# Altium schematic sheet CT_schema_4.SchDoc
size 461 x 327 mm
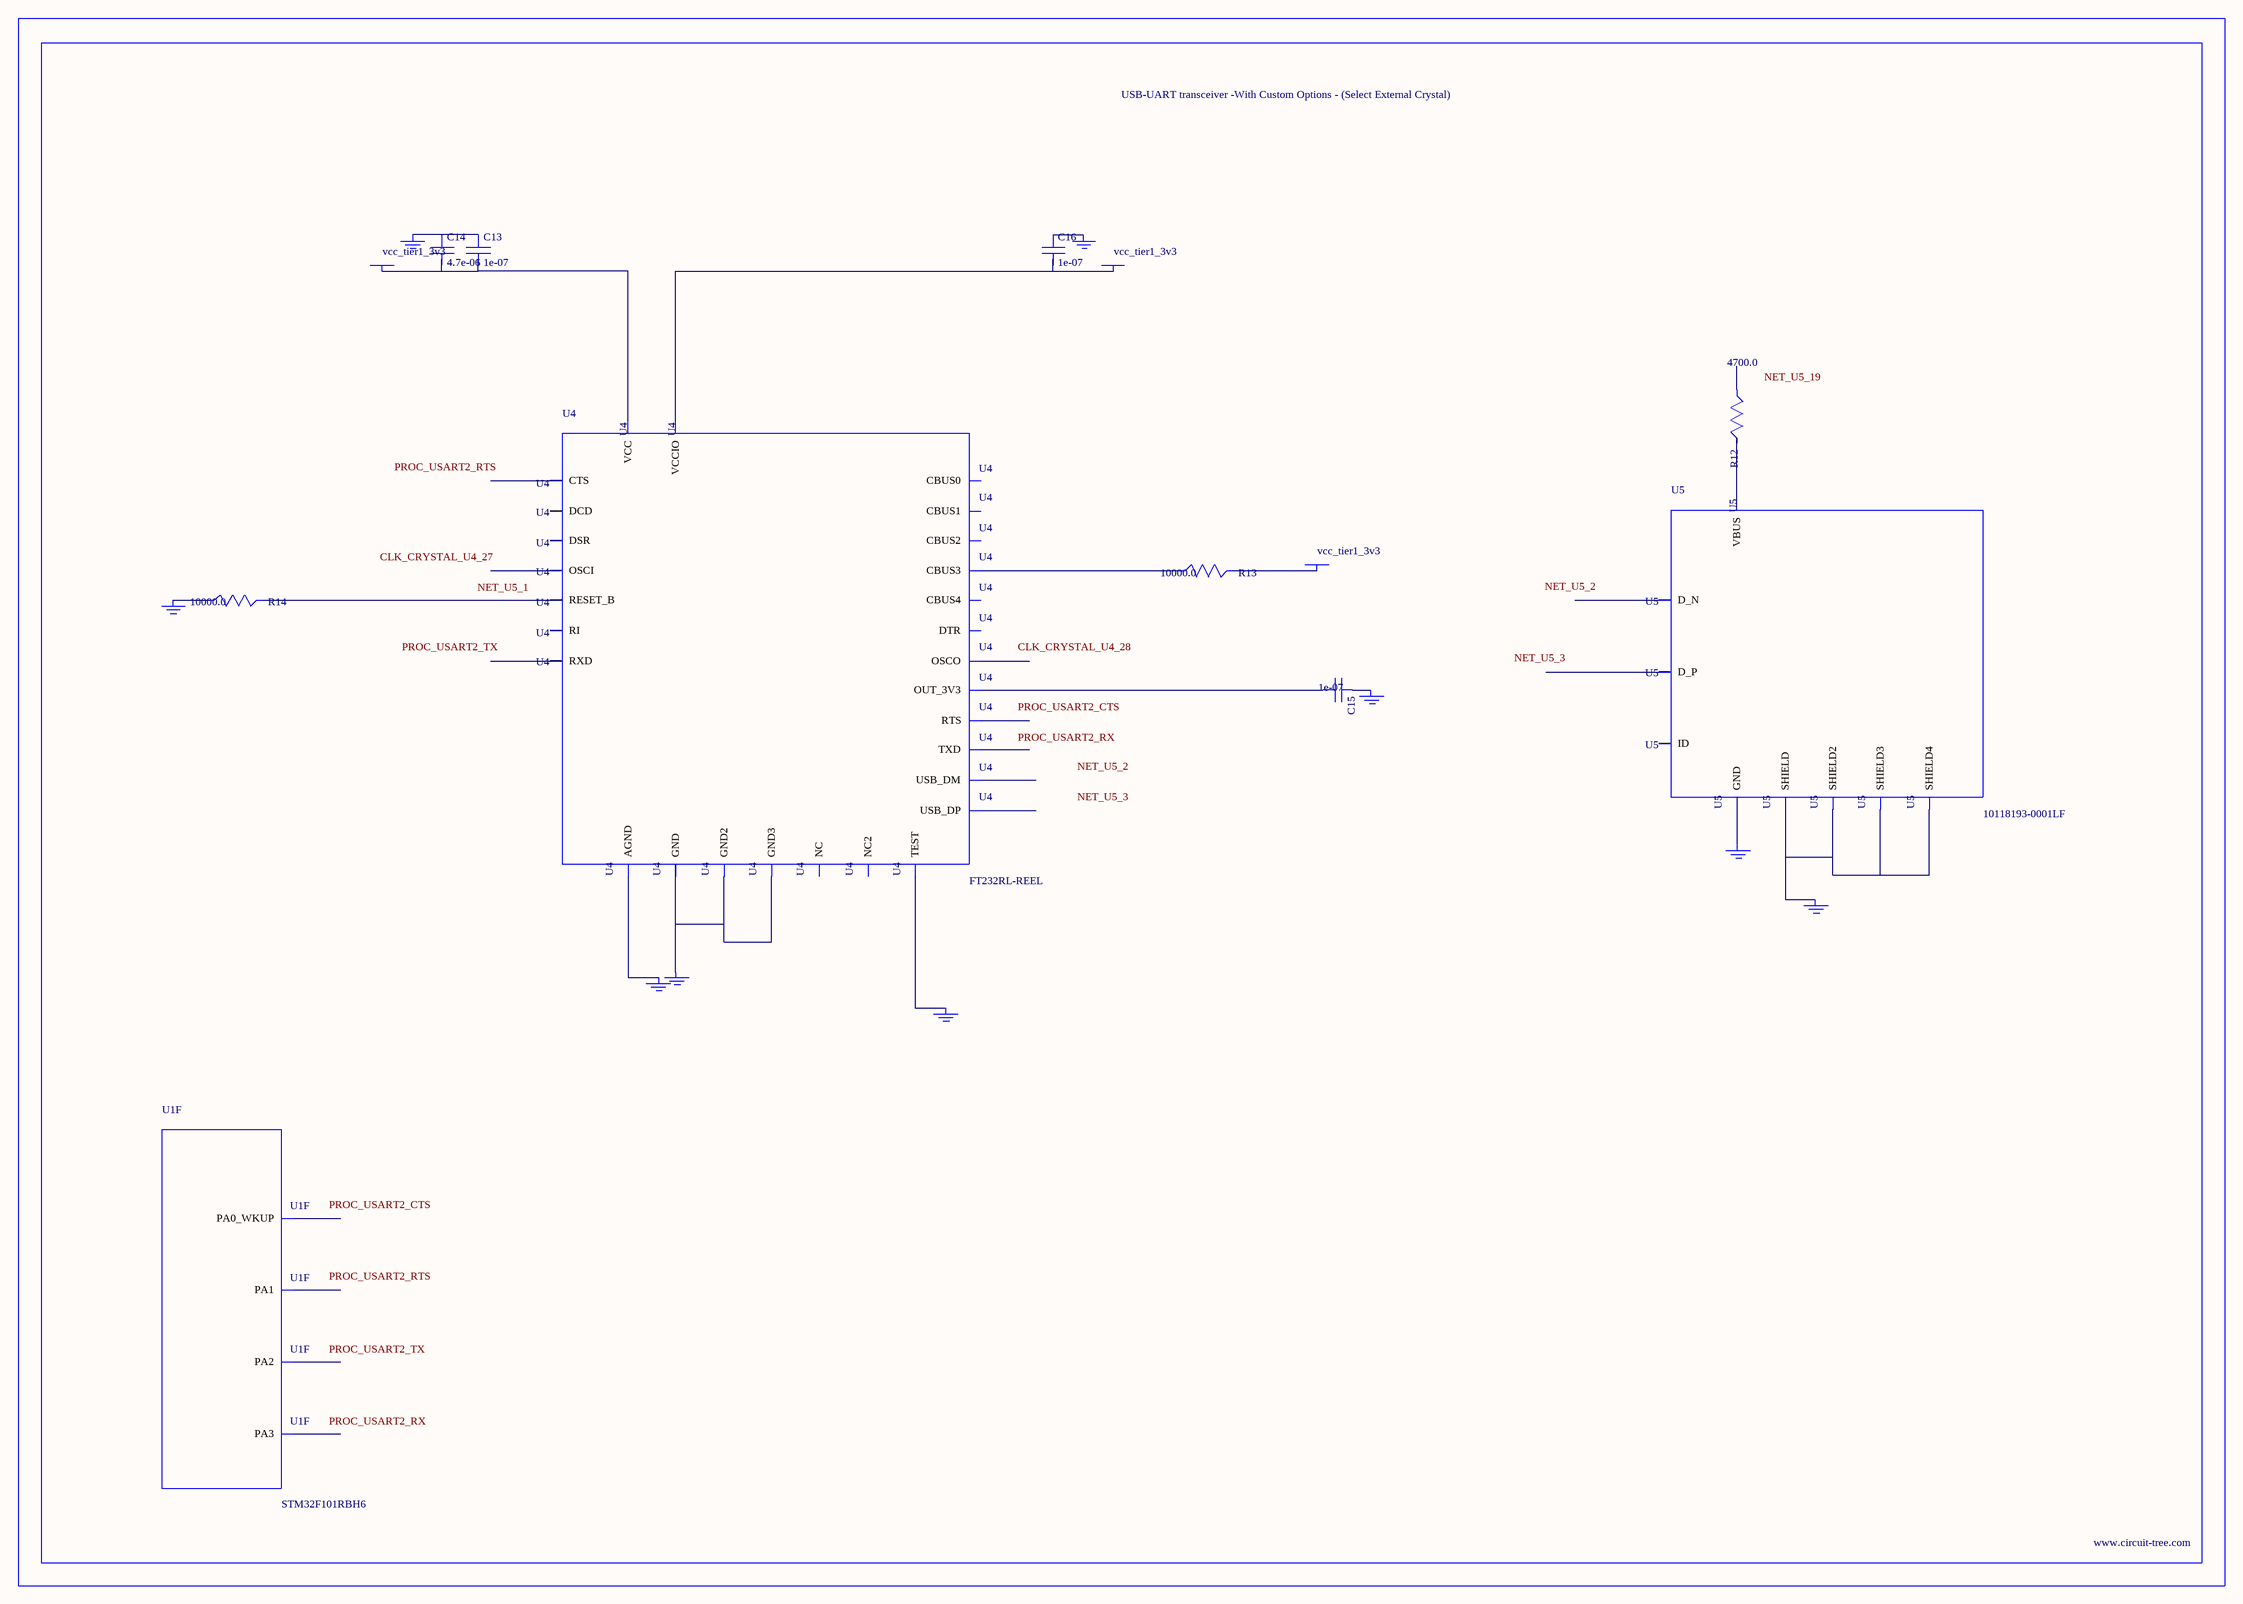
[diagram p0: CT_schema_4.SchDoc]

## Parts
BORDER3  (no value)
C13  1e-07  [C0402]
C14  4.7e-06  [C0805]
C15  1e-07  [C0402]
C16  1e-07  [C0402]
GND_INSTANCE_3_0  (no value)
GND_INSTANCE_3_1  (no value)
GND_INSTANCE_3_2  (no value)
GND_INSTANCE_3_3  (no value)
GND_INSTANCE_3_4  (no value)
GND_INSTANCE_3_5  (no value)
GND_INSTANCE_3_6  (no value)
GND_INSTANCE_3_7  (no value)
GND_INSTANCE_3_8  (no value)
POWER_INSTANCE_3_0  vcc_tier1_3v3
POWER_INSTANCE_3_1  vcc_tier1_3v3
POWER_INSTANCE_3_2  vcc_tier1_3v3
R12  4700.0  [R0603]
R13  10000.0  [R0603]
R14  10000.0  [R0603]
U1  STM32F101RBH6  [TFBGA64]  (part F of 7)
U4  FT232RL-REEL  [SSOP-28]
U5  10118193-0001LF  [FCI_10118193-0001LF]

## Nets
NetC13_1: C13.1 C14.1 GND_INSTANCE_3_3.0(GND)
NetC13_2: C13.2 C14.2 POWER_INSTANCE_3_2.0(PWR) U4.20(VCC)
NetC15_1: C15.1 GND_INSTANCE_3_1.0(GND)
NetC15_2: C15.2 U4.17(OUT_3V3)
NetC16_1: C16.1 GND_INSTANCE_3_0.0(GND)
NetC16_2: C16.2 POWER_INSTANCE_3_0.0(PWR) U4.4(VCCIO)
NetGND_INSTANCE_3_2_0: GND_INSTANCE_3_2.0(GND) R14.1
NetGND_INSTANCE_3_4_0: GND_INSTANCE_3_4.0(GND) U4.25(AGND)
NetGND_INSTANCE_3_5_0: GND_INSTANCE_3_5.0(GND) U4.26(TEST)
NetGND_INSTANCE_3_6_0: GND_INSTANCE_3_6.0(GND) U4.7(GND) U4.18(GND2) U4.21(GND3)
NetGND_INSTANCE_3_7_0: GND_INSTANCE_3_7.0(GND) U5.6(SHIELD) U5.7(SHIELD2) U5.8(SHIELD3) U5.9(SHIELD4)
NetGND_INSTANCE_3_8_0: GND_INSTANCE_3_8.0(GND) U5.5(GND)
NetPOWER_INSTANCE_3_1_0: POWER_INSTANCE_3_1.0(PWR) R13.2
NetR12_2: R12.2 U5.1(VBUS)
NetR13_1: R13.1 U4.14(CBUS3)
NetR14_2: R14.2 U4.19(RESET_B)

Not connected (* = marked no-connect by the designer): R12 1; U1 F3(PA2) G2(PA0_WKUP) G3(PA3) H2(PA1); U4 1(TXD) 2(DTR) 3(RTS) 5(RXD) 6(RI) 8(NC) 9(DSR) 10(DCD) 11(CTS) 12(CBUS4) 13(CBUS2) 15(USB_DP) 16(USB_DM) 22(CBUS1) 23(CBUS0) 24(NC2) 27(OSCI) 28(OSCO); U5 2(D_N) 3(D_P) 4(ID)

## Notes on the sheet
- Labels drawn without touching a wire or pin: CLK_CRYSTAL_U4_27, CLK_CRYSTAL_U4_28, NET_U5_1, NET_U5_2, NET_U5_3, NET_U5_19, PROC_USART2_CTS, PROC_USART2_RTS, PROC_USART2_RX, PROC_USART2_TX

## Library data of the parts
BORDER3 = BORDER_PAGE3
C13 C15 C16 = C0402C104K3RACTU
C14 = C0805C475K4RACTU
GND_INSTANCE_3_0-GND_INSTANCE_3_8 = GND
POWER_INSTANCE_3_0-POWER_INSTANCE_3_2 = PWR
R12 = RC0603JR-074K7L
R13 R14 = RC0603JR-0710KL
